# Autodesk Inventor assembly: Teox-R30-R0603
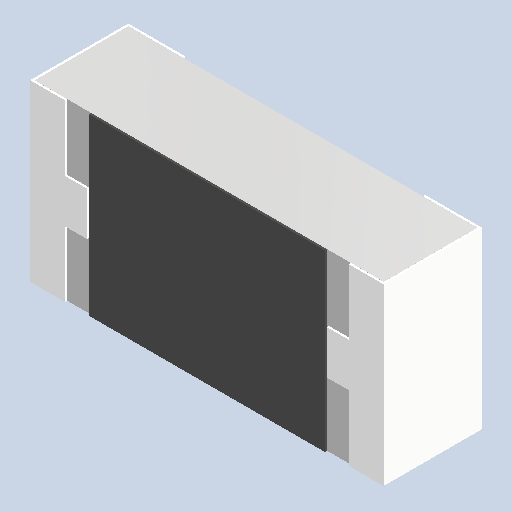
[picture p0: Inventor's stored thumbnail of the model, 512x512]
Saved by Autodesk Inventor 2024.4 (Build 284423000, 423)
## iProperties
Created: 2025-05
Part Number: Teox-R30-R0603
Document SubType Name: Assembly
Designer: AdminForWorker
Title: Teox-R30-R0603
Author: AdminForWorker
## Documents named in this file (2)
- c:\worker\convert-fusion-r02-cosv3\tmp\job-1\2\temp\files\be827049-a7f2-47ea-a815-8d9efd6bfce9\Teox-R30-R0603.iam
- c:\worker\convert-fusion-r02-cosv3\tmp\job-1\2\temp\files\be827049-a7f2-47ea-a815-8d9efd6bfce9\COMPOUND (2).ipt
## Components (1 placed, 1 different names)
1. COMPOUND (2):1
